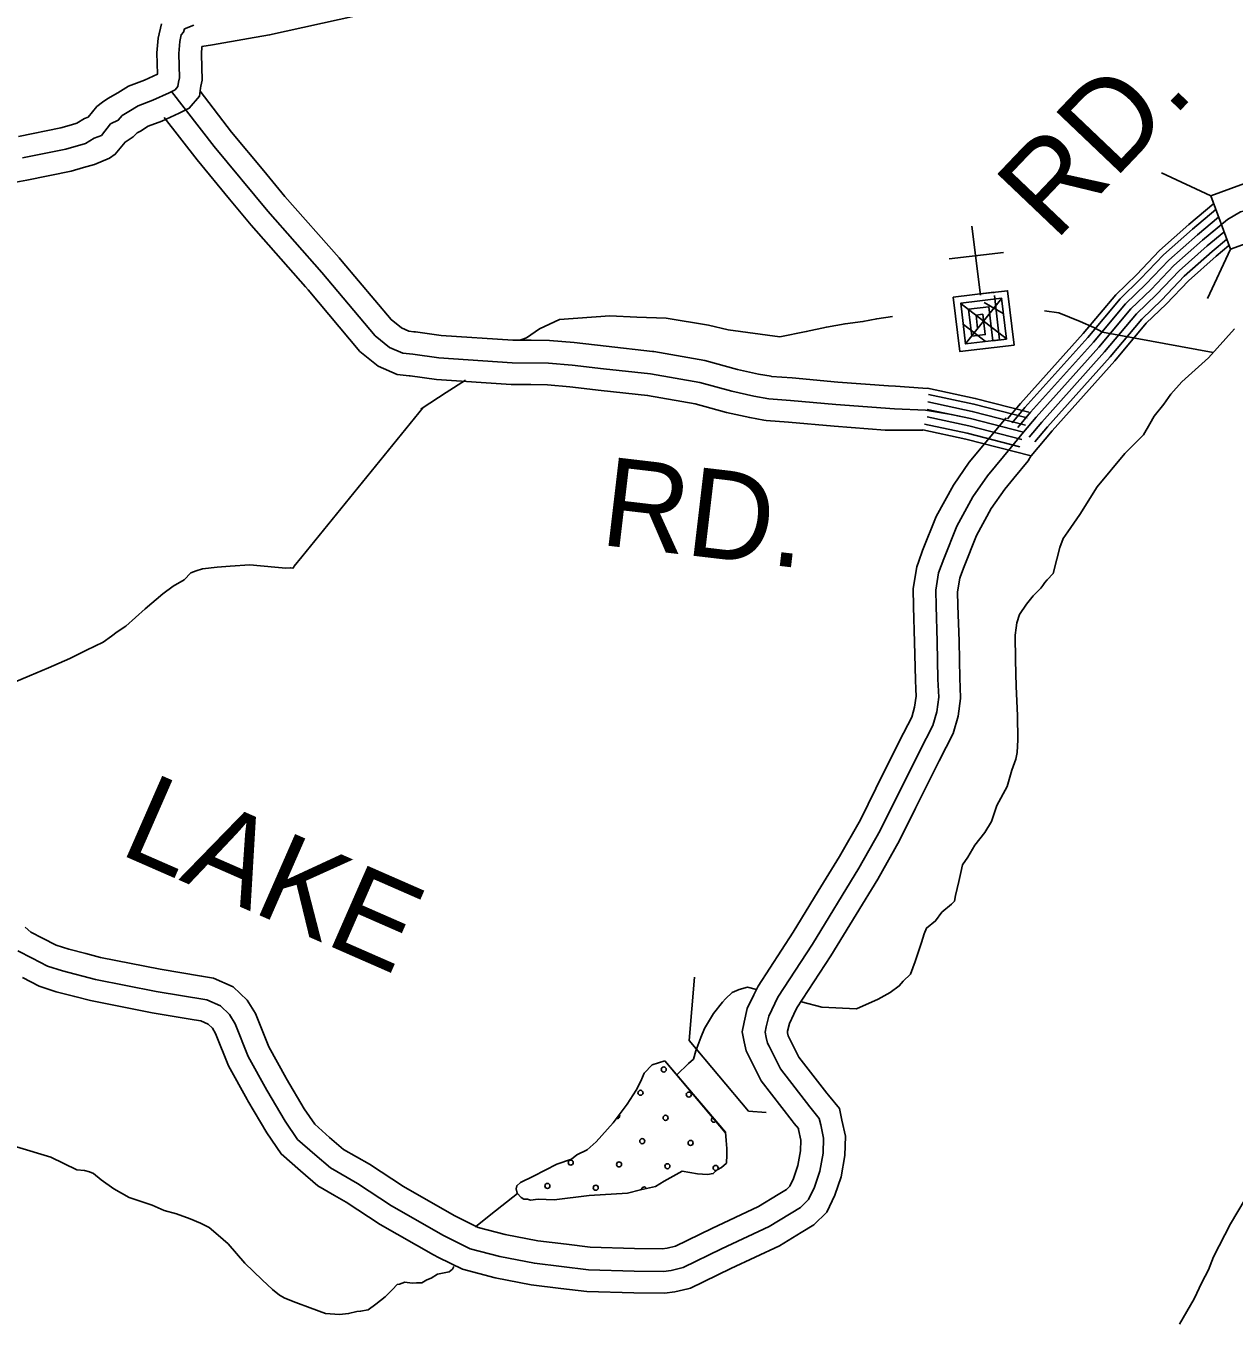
# Model space of a CAD drawing. Extents: x 1551132 to 1791609, y 378168 to 563823.
# Drawn here: x 1635413 to 1640452, y 410337 to 415751 of the extents above; entities that cross this region are included whole.
import ezdxf

# ---------------------------------------------------------------- set-up
doc = ezdxf.new("R2010")
doc.units = 0
for name, color, linetype in [('DESIGN - ROW - Right-of-Way and Easement Labels', 7, 'Continuous'), ('DESIGN - SCRATCH - User 1', 7, 'Continuous'), ('DESIGN - TRAFFIC CONTROL PERMANENT - Pavement Marking Text', 7, 'Continuous'), ('DESIGN - TRANSPORTATION - Edge of Traveled Way', 7, 'Continuous'), ('DESIGN - TRANSPORTATION - Text', 7, 'Continuous'), ('DESIGN - UTILITIES - Cable (Underground) with Text', 7, 'Continuous'), ('SURVEY - DRAINAGE - Storm Sewer', 7, 'Continuous'), ('SURVEY - PROPERTY - Owners', 7, 'Continuous'), ('SURVEY - TRANSPORTATION - Roads', 7, 'Continuous')]:
    doc.layers.add(name, color=color, linetype=linetype)

msp = doc.modelspace()

# ---------------------------------------------------------------- linework, layer by layer
at = {"layer": 'DESIGN - SCRATCH - User 1'}
for points in [[(1637991.016, 411383.921), (1638024.548, 411418.989), (1638077.747, 411435.631)], [(1638077.747, 411435.631), (1638331.024, 411137.015), (1638332.924, 411103.164), (1638336.582, 411068.863), (1638336.407, 411042.821), (1638334.183, 411008.778), (1638314.066, 410990.894), (1638296.008, 410981.002), (1638279.9, 410965.093), (1638255.876, 410961.26), (1638213.894, 410963.56), (1638150.02, 410974.685)], [(1638150.02, 410974.685), (1638074.147, 410932.817), (1638038.006, 410911.042), (1637975.916, 410897.458), (1637921.834, 410883.816), (1637761.762, 410872.932), (1637615.658, 410855.94), (1637549.676, 410858.407), (1637517.652, 410854.632), (1637505.11, 410858.099), (1637489.686, 410858.84), (1637477.719, 410864.932), (1637461.845, 410883.074), (1637457.961, 410901.133), (1637459.895, 410913.883), (1637476.128, 410927.042), (1637530.31, 410954.701), (1637626.632, 411004.102), (1637688.764, 411025.695), (1637710.88, 411043.57), (1637753.013, 411063.304), (1637791.229, 411097.088), (1637861.752, 411176.724), (1637920.259, 411254.434), (1637958.633, 411312.252), (1637976.883, 411350.187), (1637991.016, 411383.921)]]:
    msp.add_lwpolyline(points, dxfattribs=at)
at = {"layer": 'DESIGN - TRAFFIC CONTROL PERMANENT - Pavement Marking Text'}
for centre in [(1638073.182, 411398.908), (1638073.182, 411398.908), (1637976.11, 411301.836), (1637976.11, 411301.836), (1638177.72, 411294.369), (1638177.72, 411294.369), (1638080.649, 411197.298), (1638080.649, 411197.298), (1637983.577, 411100.226), (1637983.577, 411100.226), (1638185.187, 411092.759), (1638185.187, 411092.759), (1637684.895, 411010.621), (1637684.895, 411010.621), (1637886.505, 411003.154), (1637886.505, 411003.154), (1638088.116, 410995.687), (1638088.116, 410995.687), (1637587.824, 410913.55), (1637587.824, 410913.55), (1637789.434, 410906.083), (1637789.434, 410906.083)]:
    msp.add_circle(centre, 10.56, dxfattribs=at)
for centre, start, end in [((1637879.038, 411204.765), 249.845111, 36.203516), ((1638282.259, 411189.831), 113.649461, 326.957729), ((1638289.726, 410988.22), 326.425313, 289.381445), ((1637991.044, 410898.616), 23.823671, 180.857695)]:
    msp.add_arc(centre, 10.56, start, end, dxfattribs=at)
at = {"layer": 'DESIGN - TRANSPORTATION - Edge of Traveled Way'}
for p, q in [((1638178.861, 411520.483), (1638201.869, 411783.507)), ((1638178.861, 411520.483), (1638426.155, 411225.75)), ((1638077.747, 411435.631), (1638329.424, 411135.673)), ((1638426.155, 411225.75), (1638500.887, 411219.217))]:
    msp.add_line(p, q, dxfattribs=at)
at = {"layer": 'DESIGN - TRANSPORTATION - Text'}
for points in [[(1639661.028, 414563.339), (1639721.202, 414554.314), (1639809.567, 414518.371), (1639867.407, 414493.92), (1639903.273, 414473.637), (1640365.079, 414389.551)], [(1637476.596, 414442.726), (1637477.155, 414442.759), (1637501.204, 414450.601), (1637554.894, 414488.311), (1637638.026, 414527.445), (1637848.313, 414542.121), (1637960.785, 414537.229), (1638083.04, 414532.337), (1638259.086, 414502.986), (1638342.218, 414483.419), (1638557.196, 414455.135), (1638667.335, 414476.386), (1638751.458, 414495.82), (1638829.54, 414509.295), (1638903.604, 414518.779), (1638961.678, 414530.388), (1639027.452, 414539.796)], [(1638647.284, 411681.904), (1638732.199, 411659.037), (1638877.378, 411651.687), (1638967.101, 411692.055), (1639017.284, 411719.747), (1639055.466, 411747.523), (1639071.599, 411767.44), (1639101.79, 411797.274), (1639122.131, 411849.217), (1639148.656, 411929.161), (1639158.889, 411965.145), (1639169.047, 411989.113), (1639207.238, 412018.888), (1639233.47, 412054.764), (1639273.694, 412088.532), (1639285.769, 412100.466), (1639289.927, 412124.475), (1639304.302, 412182.468), (1639312.552, 412220.477), (1639318.76, 412252.478), (1639340.968, 412284.379), (1639371.301, 412334.238), (1639411.65, 412388.048), (1639439.949, 412433.916), (1639462.382, 412499.868), (1639504.898, 412579.695), (1639525.347, 412647.663), (1639541.647, 412693.623), (1639547.83, 412721.624), (1639550.172, 412773.692), (1639548.838, 412875.869), (1639543.622, 412996.098), (1639540.347, 413106.3), (1639539.031, 413210.478), (1639543.222, 413240.504), (1639545.372, 413262.521), (1639557.589, 413296.489), (1639585.88, 413340.357), (1639614.096, 413374.216), (1639646.303, 413406.042), (1639654.386, 413418), (1639662.461, 413429.967), (1639672.544, 413441.909), (1639696.71, 413467.785), (1639713.102, 413527.762), (1639725.418, 413575.755), (1639739.668, 413613.714), (1639757.842, 413641.631), (1639808.316, 413713.392), (1639881.073, 413829.07), (1639995.979, 413968.482), (1640074.485, 414046.051), (1640100.785, 414091.935), (1640118.992, 414123.861), (1640159.317, 414173.654), (1640187.591, 414215.522), (1640233.923, 414267.281), (1640344.571, 414366.659), (1640453.368, 414488.087)], [(1637059.314, 414153.418), (1637065.297, 414157.21), (1637165.72, 414222.604), (1637246.426, 414274.022)], [(1635301.705, 412987.787), (1635428.043, 413040.98), (1635506.267, 413074.481), (1635596.514, 413113.907), (1635664.738, 413147.483), (1635734.953, 413181.034), (1635769.119, 413206.834), (1635793.235, 413224.693), (1635829.392, 413248.477), (1635909.857, 413320.021), (1635984.272, 413383.597), (1636026.48, 413415.357), (1636072.645, 413441.066), (1636100.836, 413470.916), (1636122.886, 413478.775), (1636148.935, 413486.6), (1636210.984, 413494.175), (1636265.007, 413497.801), (1636347.039, 413503.226), (1636450.978, 413494.476), (1636496.952, 413490.142), (1636514.96, 413492.017), (1636526.951, 413489.934), (1636531.001, 413497.917), (1636563.259, 413537.752), (1637069.639, 414160.035)], [(1638387.282, 411732.705), (1638422.523, 411742.431), (1638459.663, 411732.43)], [(1638127.371, 411377.121), (1638176.736, 411424.639), (1638196.853, 411442.523), (1638207.077, 411476.507), (1638227.444, 411532.45), (1638243.685, 411570.401), (1638280.092, 411632.244), (1638318.408, 411680.046), (1638330.491, 411693.988), (1638358.666, 411719.83), (1638387.282, 411732.705)], [(1637991.016, 411383.921), (1638024.548, 411418.989), (1638077.747, 411435.631)], [(1638077.747, 411435.631), (1638331.024, 411137.015), (1638332.924, 411103.164), (1638336.582, 411068.863), (1638336.407, 411042.821), (1638334.183, 411008.778), (1638314.066, 410990.894), (1638296.008, 410981.002), (1638279.9, 410965.093), (1638255.876, 410961.26), (1638213.894, 410963.56), (1638150.02, 410974.685)], [(1638150.02, 410974.685), (1638074.147, 410932.817), (1638038.006, 410911.042), (1637975.916, 410897.458), (1637921.834, 410883.816), (1637761.762, 410872.932), (1637615.658, 410855.94), (1637549.676, 410858.407), (1637517.652, 410854.632), (1637505.11, 410858.099), (1637489.686, 410858.84), (1637477.719, 410864.932), (1637461.845, 410883.074), (1637457.961, 410901.133), (1637459.895, 410913.883), (1637476.128, 410927.042), (1637530.31, 410954.701), (1637626.632, 411004.102), (1637688.764, 411025.695), (1637710.88, 411043.57), (1637753.013, 411063.304), (1637791.229, 411097.088), (1637861.752, 411176.724), (1637920.259, 411254.434), (1637958.633, 411312.252), (1637976.883, 411350.187), (1637991.016, 411383.921)], [(1635373.177, 411076.17), (1635516.89, 411033.085), (1635624.546, 410980.234), (1635656.528, 410978.009), (1635678.486, 410971.842), (1635694.444, 410965.717), (1635726.269, 410939.45), (1635780.017, 410901.007), (1635843.774, 410864.498), (1635939.572, 410833.772), (1635989.421, 410811.38), (1636041.328, 410796.988), (1636097.193, 410776.562), (1636141.067, 410758.22), (1636176.95, 410739.936), (1636214.74, 410707.619), (1636256.498, 410671.26), (1636325.963, 410590.641), (1636397.511, 410522.022), (1636441.252, 410481.646), (1636471.092, 410457.396), (1636493.009, 410445.22), (1636538.883, 410426.862), (1636598.739, 410404.403), (1636662.588, 410381.919), (1636720.553, 410377.494), (1636758.577, 410381.236), (1636792.627, 410389.002), (1636808.643, 410390.894), (1636840.675, 410396.678), (1636872.833, 410420.487), (1636911.024, 410450.271), (1636941.231, 410482.105), (1636961.364, 410501.997), (1636971.372, 410503.931), (1636993.43, 410511.781), (1637023.396, 410507.564), (1637041.412, 410509.439), (1637063.404, 410509.289), (1637085.486, 410521.148), (1637103.536, 410529.031), (1637129.635, 410544.873), (1637177.701, 410554.549), (1637191.776, 410566.466), (1637197.209, 410577.174)], [(1637286.64, 410742.345), (1637294.965, 410748.037), (1637351.264, 410793.713), (1637463.478, 410881.207)], [(1640497.565, 410857.542), (1640436.908, 410755.806), (1640366.001, 410618.085), (1640345.652, 410564.142), (1640317.302, 410510.249), (1640284.853, 410442.372), (1640224.746, 410337.37)]]:
    msp.add_lwpolyline(points, dxfattribs=at)
at = {"layer": 'DESIGN - UTILITIES - Cable (Underground) with Text'}
msp.add_line((1639490.057, 414807.028), (1639263.476, 414780.25), dxfattribs=at)
for points in [[(1639357.627, 414916.038), (1639394.398, 414628.106)], [(1639393.098, 414638.773), (1639393.714, 414633.823), (1639507.117, 414647.366), (1639534.02, 414420.686), (1639307.423, 414393.817), (1639280.645, 414620.255), (1639450.332, 414640.641), (1639450.824, 414636.44)], [(1639452.183, 414626.582), (1639473.918, 414442.253), (1639332.323, 414425.526), (1639312.229, 414595.496), (1639482.2, 414615.69), (1639502.294, 414445.778), (1639445.651, 414438.627), (1639428.999, 414580.531), (1639343.889, 414570.579), (1639357.415, 414457.219), (1639413.958, 414464.003), (1639403.765, 414548.846), (1639375.631, 414545.596), (1639382.382, 414488.903)], [(1639483.525, 414615.774), (1639330.507, 414424.167)], [(1639313.271, 414592.421), (1639500.902, 414447.67)], [(1639409.523, 414598.031), (1639488.442, 414552.005)], [(1639323.722, 414505.711), (1639414.358, 414437.419)]]:
    msp.add_lwpolyline(points, dxfattribs=at)
at = {"layer": 'SURVEY - DRAINAGE - Storm Sewer'}
for p, q in [((1640355.265, 415043.33), (1640149.42, 415139.3)), ((1640436.529, 414820.073), (1640340.551, 414614.203))]:
    msp.add_line(p, q, dxfattribs=at)
msp.add_lwpolyline([(1640436.529, 414820.073), (1640659.803, 414901.337), (1640578.53, 415124.585), (1640355.265, 415043.33)], close=True, dxfattribs=at)
at = {"layer": 'SURVEY - PROPERTY - Owners'}
for points in [[(1636788.338, 415793.786), (1636429.33, 415713.842), (1636341.515, 415698.892), (1636191.46, 415673.324), (1636147.128, 415665.091), (1636144.453, 415634.365), (1636147.936, 415525.629), (1636142.228, 415500.712), (1636141.128, 415491.395), (1636137.278, 415458.877), (1636093.637, 415408.651), (1636051.455, 415387.917), (1635979.19, 415354.533), (1635922.516, 415333.057), (1635890.384, 415313.065), (1635876.151, 415305.056), (1635859.86, 415289.247), (1635826.419, 415267.38), (1635785.486, 415216.362), (1635761.437, 415200.637), (1635699.33, 415174.194), (1635653.506, 415161.152), (1635601.649, 415146.377), (1635417.003, 415108.809), (1635230.991, 415074.6)], [(1635977.815, 415760.735), (1635964.541, 415700.783), (1635959.199, 415639.448), (1635962.049, 415550.404), (1635907.534, 415525.22), (1635840.11, 415499.67), (1635796.144, 415472.319), (1635754.712, 415449.018), (1635731.904, 415433.643), (1635707.888, 415415.267), (1635672.072, 415370.625), (1635657.389, 415364.874), (1635625.015, 415345.399), (1635602.832, 415339.082), (1635557.8, 415326.248), (1635381.829, 415290.447)], [(1636112.854, 415754.627), (1636074.755, 415738.893), (1636070.655, 415724.909), (1636060.588, 415714.975), (1636054.389, 415686.983), (1636050.03, 415636.957), (1636053.305, 415534.804), (1636049.18, 415516.812), (1636047.055, 415498.803), (1636034.956, 415484.878), (1636010.881, 415473.044), (1635942.666, 415441.527), (1635880.517, 415417.976), (1635842.352, 415394.234), (1635814.252, 415378.433), (1635798.111, 415358.533), (1635766.003, 415342.757), (1635727.679, 415294.989), (1635697.597, 415283.206), (1635661.456, 415261.455), (1635579.299, 415238.054), (1635399.079, 415201.387)], [(1636020.498, 415477.769), (1636197.252, 415249.338), (1636421.28, 414979.29), (1636647.416, 414723.233), (1636869.494, 414459.201), (1636929.134, 414410.692), (1636984.949, 414386.233), (1637026.907, 414381.908), (1637134.779, 414367.057), (1637440.572, 414346.699), (1637592.527, 414345.532), (1637690.449, 414336.773), (1637822.313, 414321.748), (1638018.117, 414300.223), (1638223.82, 414264.605), (1638357.525, 414227.538), (1638449.357, 414206.804), (1638511.272, 414196.32), (1638601.203, 414189.62), (1638791.04, 414172.153), (1639034.86, 414154.261), (1639164.798, 414149.261), (1639264.654, 414132.477), (1639272.037, 414130.911)], [(1636138.828, 415478.928), (1636270.842, 415308.315), (1636404.638, 415147.027), (1636492.92, 415040.616), (1636718.847, 414784.793), (1636731.597, 414769.634), (1636935.909, 414526.728), (1636978.7, 414491.919), (1637009.282, 414478.518), (1637030.282, 414476.352), (1637038.181, 414475.543), (1637144.354, 414460.926), (1637444.072, 414440.968), (1637519.587, 414440.393), (1637597.093, 414439.793), (1637699.991, 414430.593), (1637832.805, 414415.459), (1638026.692, 414394.142), (1638031.275, 414393.642), (1638244.511, 414356.724), (1638380.517, 414319.015), (1638467.623, 414299.348), (1638520.93, 414290.323), (1638522.655, 414290.031), (1638609.028, 414283.589), (1638798.815, 414266.131), (1639010.385, 414250.605), (1639040.118, 414248.422), (1639153.123, 414241.388), (1639176.265, 414239.38)], [(1635989.64, 415369.425), (1636126.462, 415192.603), (1636262.267, 415028.899), (1636352.364, 414920.288), (1636578.701, 414664.015), (1636590.009, 414650.556), (1636805.604, 414394.241), (1636881.452, 414332.548), (1636961.541, 414297.455), (1637011.299, 414292.322), (1637016.065, 414291.83), (1637125.571, 414276.755), (1637437.205, 414256.013), (1637518.162, 414255.388), (1637588.127, 414254.855), (1637681.275, 414246.521), (1637812.222, 414231.604), (1638005.442, 414210.354), (1638203.921, 414175.995), (1638335.409, 414139.535), (1638431.782, 414117.776), (1638490.081, 414107.901), (1638500.322, 414106.176), (1638593.678, 414099.218), (1638783.565, 414081.751), (1638996.852, 414066.092), (1639042.418, 414065.225), (1639154.123, 414065.225)], [(1639573.914, 414056.642), (1639626.487, 414119.694), (1639888.506, 414412.06), (1640021.603, 414571.239), (1640106.168, 414652.7), (1640200.849, 414752.102), (1640319.572, 414857.322), (1640424.169, 414944.633), (1640478.385, 414976.259), (1640570.532, 414999.584), (1640640.606, 415013.068), (1640744.653, 415022.285), (1640938.64, 415026.802), (1641176.593, 415026.985), (1641402.446, 415033.861)], [(1639273.154, 414130.669), (1639352.502, 414113.785), (1639573.914, 414056.642)], [(1639136.823, 413519.261), (1639152.456, 413563.037), (1639209.964, 413706.091), (1639281.612, 413836.511), (1639347.594, 413931.989), (1639390.751, 413983.94), (1639451.158, 414056.642), (1639501.49, 414117.019)], [(1635379.594, 411893.366), (1635439.367, 411862.874), (1635503.124, 411830.34), (1635564.964, 411809.847), (1635702.686, 411774.747), (1635956.272, 411724.745), (1636167.975, 411689.078), (1636223.791, 411664.619), (1636261.523, 411628.285), (1636285.247, 411590.059), (1636340.263, 411453.464), (1636417.253, 411312.702), (1636494.317, 411183.948), (1636545.766, 411107.463), (1636617.306, 411044.836), (1636682.888, 410988.26), (1636796.402, 410923.308), (1636937.707, 410830.114), (1637154.785, 410706.294), (1637266.366, 410651.376), (1637390.104, 410618.384), (1637533.884, 410591.25), (1637759.637, 410563.491), (1637949.558, 410558.033), (1638071.522, 410557.099), (1638103.546, 410560.858), (1638153.62, 410572.491), (1638314.141, 410651.36), (1638512.753, 410743.963), (1638643.292, 410823.065), (1638677.524, 410856.841), (1638701.882, 410908.717), (1638724.348, 410974.636), (1638737.698, 411049.788), (1638739.79, 411112.539), (1638727.723, 411168.849), (1638721.915, 411194.925), (1638682.266, 411243.293), (1638559.419, 411402.43), (1638512.104, 411496.916), (1638506.187, 411508.975), (1638500.362, 411533.05), (1638496.521, 411555.109), (1638500.679, 411577.101), (1638510.987, 411621.078), (1638549.545, 411700.88), (1638693.083, 411922.069), (1638887.295, 412238.977), (1638976.393, 412396.498), (1639140.706, 412727.657), (1639195.447, 412833.368), (1639211.855, 412891.32), (1639220.28, 412951.33), (1639216.821, 413027.448), (1639213.93, 413183.669), (1639208.98, 413331.898), (1639207.455, 413397.991), (1639219.722, 413471.018), (1639240.629, 413529.586), (1639295.337, 413665.657), (1639361.927, 413786.877), (1639422.792, 413874.946), (1639523.631, 413996.324), (1639573.914, 414056.642)], [(1639311.044, 413457.051), (1639325.452, 413497.402), (1639377.46, 413626.756), (1639439.192, 413739.125), (1639495.132, 413820.069), (1639533.039, 413865.712), (1639593.346, 413938.297), (1639605.004, 413960.031)], [(1635409.985, 411993.002), (1635433.559, 411971.693), (1635482.216, 411946.868), (1635539.59, 411917.592), (1635591.472, 411900.4), (1635662.329, 411882.341), (1635723.461, 411866.757), (1635973.23, 411817.515), (1636145.334, 411788.514), (1636195.133, 411780.122), (1636277.056, 411744.229), (1636335.421, 411688.028), (1636369.662, 411632.852), (1636425.652, 411493.848), (1636497.667, 411362.178), (1636499.117, 411359.528), (1636573.941, 411234.516), (1636617.131, 411170.306), (1636679.155, 411116.013), (1636737.595, 411065.595), (1636791.535, 411034.728), (1636845.817, 411003.669), (1636987.072, 410910.508), (1637199.009, 410789.622), (1637215.5, 410781.505), (1637299.648, 410740.087), (1637411.021, 410710.395), (1637548.392, 410684.469), (1637666.981, 410669.885), (1637766.762, 410657.618), (1637951.275, 410652.318), (1638066.364, 410651.435), (1638087.338, 410653.893), (1638121.737, 410661.885), (1638273.425, 410736.412), (1638468.271, 410827.265), (1638550.636, 410877.175), (1638584.96, 410897.967), (1638599.326, 410912.151), (1638614.318, 410944.076), (1638632.776, 410998.228), (1638643.684, 411059.654), (1638645.167, 411104.106), (1638635.609, 411148.715), (1638634.759, 411152.507), (1638617.084, 411174.082), (1638608.476, 411184.583), (1638479.204, 411352.037), (1638427.622, 411455.031), (1638416.981, 411476.732), (1638407.998, 411513.85), (1638400.69, 411555.801), (1638408.414, 411596.627), (1638421.564, 411652.737), (1638449.13, 411709.771), (1638467.221, 411747.231), (1638613.327, 411972.378), (1638717.541, 412142.425), (1638806.039, 412286.837), (1638893.062, 412440.699), (1638957.71, 412570.986), (1639056.608, 412770.3), (1639107.324, 412868.244), (1639119.374, 412910.812), (1639125.69, 412955.788), (1639124.348, 412985.464), (1639122.574, 413024.431), (1639119.665, 413181.219), (1639114.724, 413329.239), (1639112.982, 413404.775), (1639128.115, 413494.86), (1639136.815, 413519.244)], [(1635398.143, 411782.072), (1635468.042, 411746.404), (1635539.465, 411722.737), (1635616.647, 411703.061), (1635682.703, 411686.228), (1635939.964, 411635.501), (1636114.61, 411606.076), (1636141.851, 411601.492), (1636172.55, 411588.034), (1636190.433, 411570.808), (1636204.041, 411548.891), (1636258.123, 411414.621), (1636335.329, 411273.459), (1636338.504, 411267.659), (1636417.719, 411135.305), (1636477.109, 411047.011), (1636557.807, 410976.368), (1636630.256, 410913.866), (1636699.662, 410874.148), (1636748.861, 410845.998), (1636890.216, 410752.77), (1637112.244, 410626.134), (1637133.802, 410615.517), (1637234.35, 410566.032), (1637369.98, 410529.873), (1637519.926, 410501.572), (1637644.407, 410486.264), (1637752.787, 410472.939), (1637947.908, 410467.33), (1638076.48, 410466.347), (1638119.137, 410471.355), (1638173.853, 410484.064), (1638184.536, 410486.614), (1638353.307, 410569.533), (1638555.544, 410663.827), (1638646.508, 410718.954), (1638699.407, 410751.005), (1638752.748, 410803.631), (1638786.122, 410874.7), (1638812.446, 410951.935), (1638828.138, 411040.296), (1638830.813, 411120.656), (1638816.338, 411188.216), (1638805.755, 411235.726), (1638760.148, 411291.369), (1638753.256, 411299.778), (1638636.592, 411450.906), (1638593.377, 411537.209), (1638592.01, 411539.992), (1638589.219, 411551.517), (1638588.71, 411554.442), (1638589.444, 411558.318), (1638597.01, 411590.627), (1638615.701, 411629.294), (1638628.743, 411656.287), (1638769.806, 411873.668), (1638875.27, 412045.747), (1638965.46, 412192.934), (1639056.558, 412353.98), (1639123.432, 412488.759), (1639221.613, 412686.639), (1639280.22, 412799.817), (1639300.819, 412872.569), (1639311.277, 412947.038), (1639309.152, 412993.864), (1639307.486, 413030.348), (1639304.611, 413186.019), (1639299.653, 413334.456), (1639298.336, 413391.466), (1639307.844, 413448.084), (1639311.053, 413457.068)]]:
    msp.add_lwpolyline(points, dxfattribs=at)
at = {"layer": 'SURVEY - TRANSPORTATION - Roads'}
for points in [[(1639507.315, 414112.177), (1639560.881, 414176.42), (1639822.941, 414468.828), (1639958.08, 414630.449), (1640044.67, 414713.86), (1640140.592, 414814.571), (1640263.023, 414923.074), (1640367.637, 415010.401)], [(1639526.298, 414096.352), (1639579.58, 414160.253), (1639841.624, 414452.653), (1639976.188, 414613.574), (1640062.194, 414696.426), (1640157.767, 414796.762), (1640279.139, 414904.332), (1640376.179, 414985.334)], [(1639550.106, 414076.493), (1639603.03, 414139.969), (1639865.065, 414432.352), (1639998.896, 414592.406), (1640084.185, 414674.567), (1640179.308, 414774.436), (1640299.355, 414880.831), (1640387.312, 414954.241)], [(1639573.914, 414056.642), (1639626.487, 414119.694), (1639888.506, 414412.06), (1640021.603, 414571.239), (1640106.168, 414652.7), (1640200.849, 414752.102), (1640319.572, 414857.322), (1640399.253, 414923.832)], [(1639597.721, 414036.792), (1639649.945, 414099.418), (1639911.947, 414391.768), (1640044.311, 414550.072), (1640128.151, 414630.833), (1640222.39, 414729.769), (1640339.788, 414833.813), (1640409.294, 414891.84)], [(1639605.738, 413957.84), (1639692.852, 414062.317), (1639954.83, 414354.634), (1640085.86, 414511.346), (1640168.375, 414590.832), (1640261.806, 414688.918), (1640376.778, 414790.812), (1640430.636, 414835.763)], [(1639621.529, 414016.933), (1639673.395, 414079.134), (1639935.389, 414371.467), (1640067.019, 414528.905), (1640150.142, 414608.974), (1640243.932, 414707.443), (1640360.004, 414810.312), (1640420.661, 414860.947)], [(1639173.465, 414240.538), (1639372.368, 414198.221), (1639595.58, 414140.611)], [(1639174.831, 414183.295), (1639359.602, 414143.969), (1639581.663, 414086.66)], [(1639177.34, 414214.438), (1639366.71, 414174.153), (1639589.405, 414116.677)], [(1639171.523, 414152.294), (1639352.502, 414113.785), (1639573.914, 414056.642)], [(1639160.465, 414091.26), (1639338.294, 414053.417), (1639558.422, 413996.607)], [(1639171.923, 414120.51), (1639345.402, 414083.601), (1639566.164, 414026.625)], [(1639154.098, 414066.317), (1639332.403, 414028.375), (1639605.738, 413957.84)]]:
    msp.add_lwpolyline(points, dxfattribs=at)

# ---------------------------------------------------------------- texts
at = {"layer": 'DESIGN - ROW - Right-of-Way and Easement Labels'}
for s, height, rotation, p in [('RD.', 370.0012, 46.394931, (1639704.728, 414849.588)), ('RD.', 369.9915, 353.296611, (1637802.438, 413587.971)), ('LAKE', 369.9941, 336.340558, (1635795.576, 412301.277))]:
    msp.add_text(s, height=height, rotation=rotation, dxfattribs=at).set_placement(p)

doc.saveas('drawing.dxf')
